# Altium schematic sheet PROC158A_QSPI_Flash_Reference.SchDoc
size 431 x 279 mm; Date: Not shown in title block; ApprovedBy: Not shown in title block; CheckedBy: Not shown in title block; Author: Not shown in title block; CompanyName: Not shown in title block; Engineer: Not shown in title block; Organization: Not shown in title block; Address1: Not shown in title block; Address2: Not shown in title block; Address3: Not shown in title block; Address4: Not shown in title block; DocumentNumber: 5; Revision: Use project parameter SCH_Rev; SheetNumber: 5; SheetTotal: 24; PageSetup: Record=PageOptions¦CenterHorizontal=True¦CenterVertical=True¦PrintScale=1.00¦XCorrection=1.00¦YCorrection=1.00¦PrintKind=0¦BorderSize=5000000¦LeftOffset=0¦BottomOffset=0¦Orientation=2¦PaperLength=1000¦PaperWidth=1000¦Scale=100¦PaperSource=15¦PrintQuality=600¦MediaType=1¦DitherType=10¦PaperKind=Letter¦PrintScaleMode=1
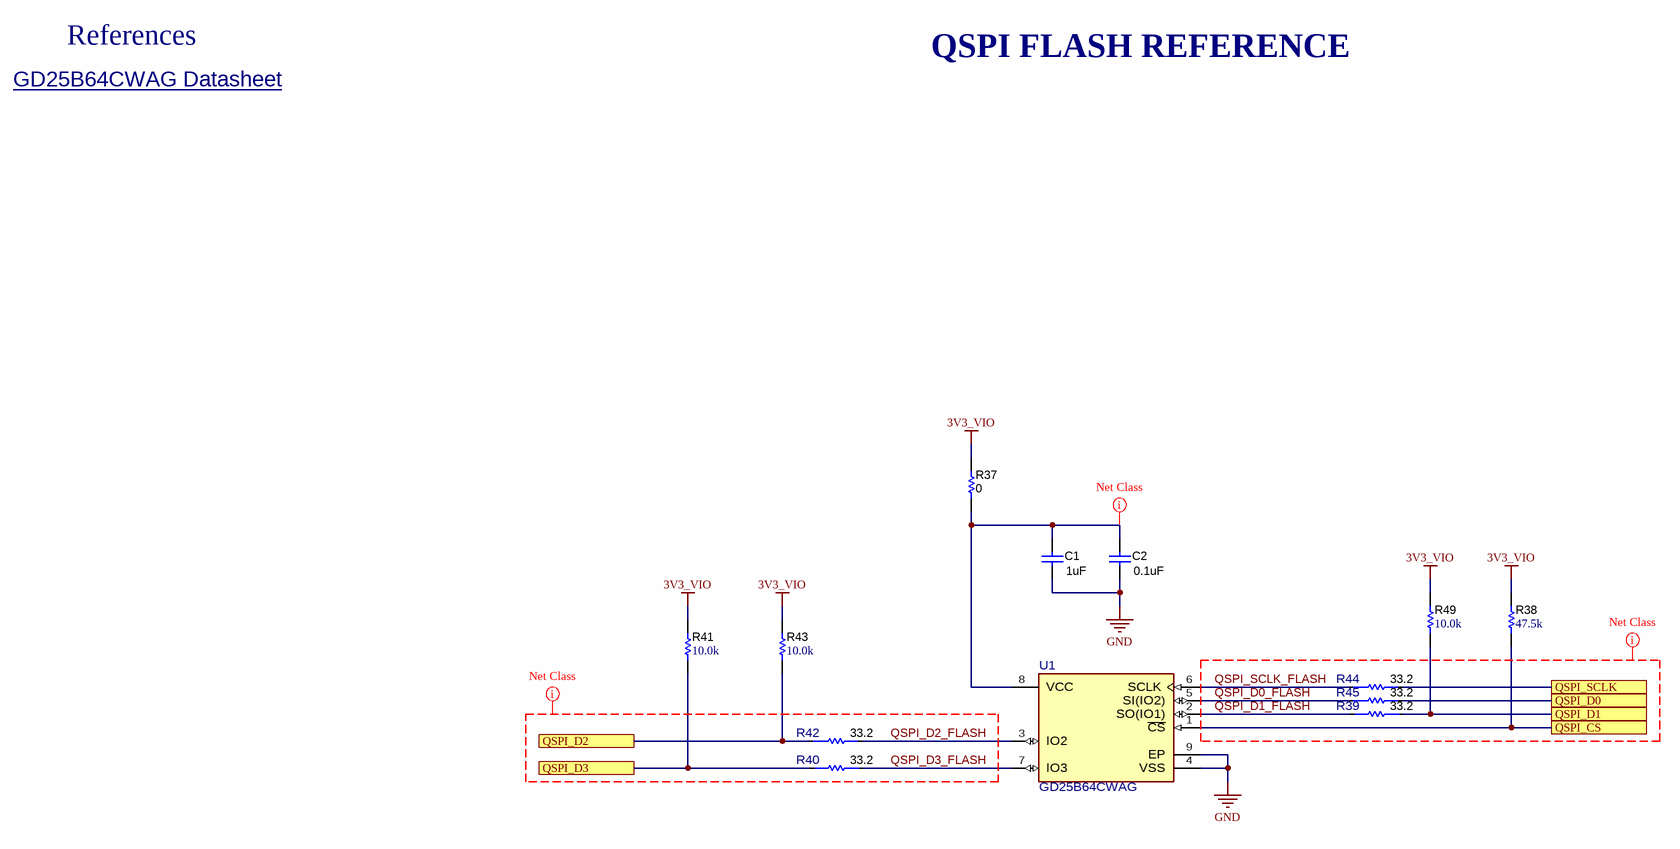
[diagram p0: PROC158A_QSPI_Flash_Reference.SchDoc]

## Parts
C1  ValueDisplayed: 1uF  [0603L]  (hidden comment: GCM188R71C105KA64D)
C2  ValueDisplayed: 0.1uF  [0402L]  (hidden comment: CGA2B3X7R1H104K050BB)
R37  ValueDisplayed: 0  [0402L]  (hidden comment: ERJ-2GE0R00X)
R38  ValueDisplayed: 47.5k  [0402L]  (hidden comment: CRCW040247K5FKED)
R39  Res_ohm: 33.2  [FP-ERJ-1GNF33R2C_0201-MFG]  (hidden comment: ERJ-1GNF33R2C)
R40  Res_ohm: 33.2  [FP-ERJ-1GNF33R2C_0201-MFG]  (hidden comment: ERJ-1GNF33R2C)
R41  ValueDisplayed: 10.0k  [0402L]  (hidden comment: CRCW040210K0FKED)
R42  Res_ohm: 33.2  [FP-ERJ-1GNF33R2C_0201-MFG]  (hidden comment: ERJ-1GNF33R2C)
R43  ValueDisplayed: 10.0k  [0402L]  (hidden comment: CRCW040210K0FKED)
R44  Res_ohm: 33.2  [FP-ERJ-1GNF33R2C_0201-MFG]  (hidden comment: ERJ-1GNF33R2C)
R45  Res_ohm: 33.2  [FP-ERJ-1GNF33R2C_0201-MFG]  (hidden comment: ERJ-1GNF33R2C)
R49  ValueDisplayed: 10.0k  [0402L]  (hidden comment: CRCW040210K0FKED)
U1  GD25B64CWAG  [FP-GD25B64CWAG_WSON8-IPC_C]

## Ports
QSPI_CS, QSPI_D0, QSPI_D1, QSPI_D2, QSPI_D3, QSPI_SCLK

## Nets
3V3_VIO: R37.1 R38.2 R41.2 R43.2 R49.2
GND: C1.1 C2.1 U1.4(VSS) U1.9(EP)
QSPI_CS: R38.1 U1.1(~{CS}) ; port QSPI_CS
QSPI_D0: R45.2 ; port QSPI_D0
QSPI_D0_FLASH: R45.1 U1.5(SI(IO2))
QSPI_D1: R39.1 R49.1 ; port QSPI_D1
QSPI_D1_FLASH: R39.2 U1.2(SO(IO1))
QSPI_D2: R42.1 R43.1 ; port QSPI_D2
QSPI_D2_FLASH: R42.2 U1.3(IO2)
QSPI_D3: R40.2 R41.1 ; port QSPI_D3
QSPI_D3_FLASH: R40.1 U1.7(IO3)
QSPI_SCLK: R44.2 ; port QSPI_SCLK
QSPI_SCLK_FLASH: R44.1 U1.6(SCLK)
NetC1_2: C1.2 C2.2 R37.2 U1.8(VCC)

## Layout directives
net class QSPI: QSPI_D0_FLASH, QSPI_D1_FLASH, QSPI_D2_FLASH, QSPI_D3_FLASH, QSPI_SCLK_FLASH
net class PWR: NetC1_2

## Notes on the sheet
- References
- QSPI FLASH REFERENCE
- GD25B64CWAG Datasheet <https://www.gigadevice.com/datasheet/gd25b64c/>

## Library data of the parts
C1 = CMP-0007136-5: CAP, CERM, 1 uF, 16 V, +/- 10%, X7R, AEC-Q200 Grade 1, 0603; Manufacturer: MuRata; TaMin_C: -55°C; Polarized: N; SizeAreaWB_mm2: 4.68; Value1: Unknown; U/M: EA; Value: 1uF; TaMax_C: 125°C; SizeZ_mm: 1; SizeX_mm: 1.6; SizeY_mm: 0.8; Cap_Case: 0603; Value2: 16V; SizeArea_mm2: 1.28; AEC Qualified: Y; Cap_F: 1µF; AEC Category: Q200
C2 = CMP-0006325-2: CAP, CERM, 0.1 uF, 50 V, +/- 10%, X7R, AEC-Q200 Grade 1, 0402; Manufacturer: TDK; TaMin_C: -55°C; ESR_ohm: 0.039064; Polarized: N; SizeAreaWB_mm2: 3; Value1: 0.039064 ohm; U/M: EA; Value: 0.1uF; TaMax_C: 125°C; SizeZ_mm: 0.6; SizeX_mm: 1; SizeY_mm: 0.5; Cap_Case: 0402; Value2: 50V; AEC Qualified: Y; Cap_F: 100nF; IRMS_A: 8.14669dA; AEC Category: Q200
R37 = CMP-0026992-3: RES, 0, 5%, 0.1 W, AEC-Q200 Grade 0, 0402; Manufacturer: Panasonic; Power_W: 100mW; TempCo: 600 ppm/C; Value_Code: 0000; Value: 0; EIA_Code: E24; SizeX_mm: 1; SizeY_mm: 0.5; SizeZ_mm: 0.6; Value2: 0.1W; AEC Qualified: Y; VDC_V: 50V; AEC Category: Q200; SizeAreaWB_mm2: 3
R38 = CMP-0026395-2: RES, 47.5 k, 1%, 0.063 W, AEC-Q200 Grade 0, 0402; Manufacturer: Vishay-Dale; Power_W: 63mW; TempCo: 100 ppm/C; Value_Code: 47k5; Value: 47.5k; EIA_Code: E96; SizeX_mm: 1; SizeY_mm: 0.5; SizeZ_mm: 0.6; Value2: 0.063W; AEC Qualified: Y; VDC_V: 50V; AEC Category: Q200; AEC Grade: 0
R39 R40 R42 R44 R45 = CMP-0089575-2: Res Thick Film 0201 33.2 Ohm 1% 0.05W(1/20W) ±200ppm/C Pad SMD Automotive T/R; Manufacturer: Panasonic; TempCo: 200ppm/°C; VDC_V: 25V; AEC Qualified: Yes; SizeZ_mm: 0.26mm; Power_W: 50mW; AEC Grade: Grade 1; Value: 33.2
R41 R43 R49 = CMP-0025958-3: RES, 10.0 k, 1%, 0.063 W, AEC-Q200 Grade 0, 0402; Manufacturer: Vishay-Dale; Power_W: 63mW; TempCo: 100 ppm/C; Value_Code: 10k0; Value: 10.0k; EIA_Code: E96; Res_ohm: 10k; SizeX_mm: 1; SizeY_mm: 0.5; SizeZ_mm: 0.6; Value2: 0.063W; AEC Qualified: Y; VDC_V: 50V; AEC Category: Q200; AEC Grade: 0
U1 = CMP-0091081-1: 3.3V Uniform Sector Dual and Quad Serial Flash SPI 64Mbit 2.7-3.6V WSON8; Manufacturer: GigaDevice; Interface: SPI,Other; Min Supply Voltage: 2.7V; TaMin_C: -40°C; AEC Grade: Grade 1; Memory Size: 64Mbits; Frequency_Fixed: 120MHz; TaMax_C: +125°C; SizeZ_mm: 0.8mm; Standoff Height: 0mm; AEC Qualified: Yes; Nominal Supply Current: 13-15mA; Max Supply Voltage: 3.6V; Access Time: 7ns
